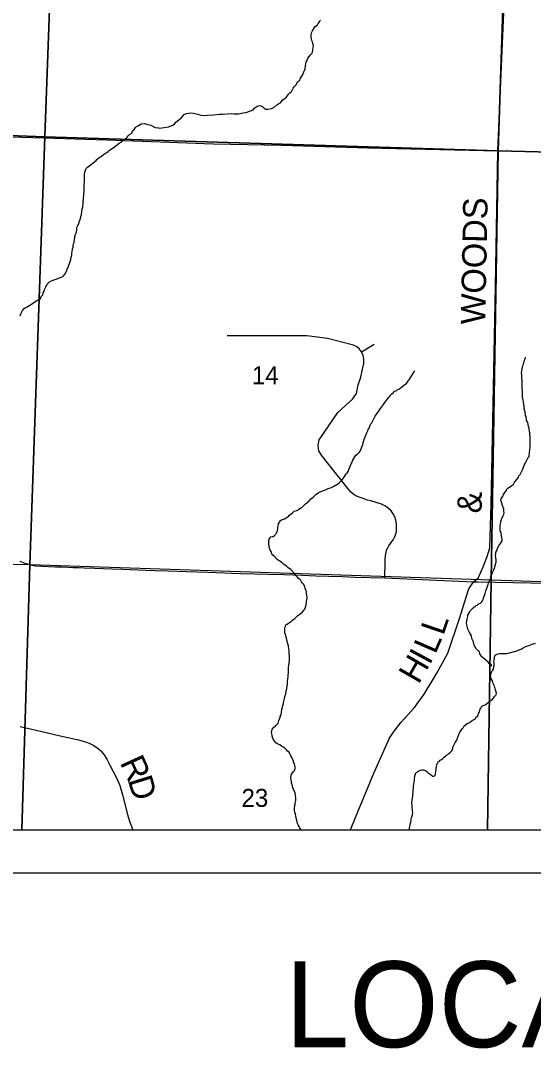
# Model space of a CAD drawing. Extents: x 0 to 34, y 0 to 22.
# Drawn here: x 3.811 to 5.004, y 13.591 to 15.984 of the extents above; entities that cross this region are included whole.
import ezdxf

# ---------------------------------------------------------------- set-up
doc = ezdxf.new("R2010")
doc.units = 0
for name, color, linetype in [('Default', 7, 'Continuous'), ('GM_X_County_Road', 7, 'Continuous'), ('GM_X_County_Road_Text', 7, 'Continuous'), ('GM_X_Minor_River', 7, 'Continuous'), ('GM_X_Section', 7, 'Continuous'), ('GM_X_Section_Text', 7, 'Continuous'), ('GM_X_Township_Road', 7, 'Continuous'), ('SH_Data', 7, 'Continuous'), ('SH_Text', 7, 'Continuous')]:
    doc.layers.add(name, color=color, linetype=linetype)

msp = doc.modelspace()

# ---------------------------------------------------------------- linework, layer by layer
at = {"layer": 'Default'}
msp.add_lwpolyline([(5.0396, 17.6997), (4.98, 17.7015), (4.9045, 17.7039), (4.763, 17.7084), (4.6735, 17.7102), (4.6237, 17.7121), (4.506, 17.7155), (4.4203, 17.718), (4.2769, 17.7222), (4.1969, 17.7246), (4.1354, 17.7264), (4.1238, 17.7269), (4.1165, 17.7286), (3.9904, 17.7296), (3.7662, 17.7368), (3.4544, 17.7458), (3.1037, 17.7609), (2.976, 17.7664), (2.8305, 17.7727), (2.1, 17.8044), (2.1, 14.1), (5.898, 14.1)], dxfattribs=at)
for points in [[(2.801, 14.1), (3.8138, 14.1), (3.832, 14.7167), (2.8159, 14.7367)], [(3.8138, 14.1), (4.8974, 14.1), (4.9059, 14.6808), (3.832, 14.7167)], [(4.8974, 14.1), (5.8991, 14.1), (5.9159, 14.648), (4.9059, 14.6808)]]:
    msp.add_lwpolyline(points, close=True, dxfattribs=at)
at = {"layer": 'GM_X_County_Road'}
for points in [[(4.5787, 14.1), (4.5919, 14.1324), (4.6325, 14.2319), (4.6697, 14.3133), (4.6805, 14.3297), (4.6967, 14.3508), (4.7273, 14.3845), (4.7499, 14.4158), (4.7797, 14.4649), (4.8049, 14.5109), (4.8331, 14.5941), (4.848, 14.6414), (4.8542, 14.6607), (4.865, 14.6774), (4.8766, 14.6871), (4.8871, 14.7118), (4.8966, 14.7365), (4.9028, 14.7566), (4.9058, 14.8573), (4.916, 15.3658), (4.9217, 15.6805), (4.9358, 16.0016), (4.9423, 16.1873)], [(3.809, 14.7251), (3.8203, 14.7206), (3.8369, 14.7159), (3.8457, 14.7142), (3.8759, 14.7126), (3.891, 14.7124), (3.9054, 14.7119), (3.9206, 14.7112), (3.9331, 14.7109), (3.9466, 14.7106), (3.9586, 14.71), (3.9826, 14.7091), (4.0229, 14.7076), (4.0487, 14.7069), (4.1027, 14.7047), (4.1237, 14.704), (4.1544, 14.7028), (4.1965, 14.7012), (4.2463, 14.6997), (4.3233, 14.697), (4.3858, 14.6949), (4.4243, 14.694), (4.4668, 14.6925), (4.4978, 14.6914), (4.5278, 14.6907), (4.5599, 14.6894), (4.5895, 14.6883), (4.6585, 14.6866), (4.865, 14.6774), (4.8751, 14.6772)], [(4.8751, 14.6772), (5.0801, 14.6733), (5.2252, 14.6674), (5.4111, 14.6617), (5.533, 14.6576), (5.764, 14.6502), (5.8816, 14.6485), (5.9165, 14.6499)], [(3.81, 14.3408), (3.8603, 14.3289), (3.9027, 14.319), (3.9456, 14.309), (3.964, 14.3037), (3.9721, 14.3006), (3.9794, 14.2972), (3.9859, 14.2932), (3.9917, 14.2887), (3.9973, 14.2839), (4.0049, 14.2747), (4.012, 14.2627), (4.0186, 14.2503), (4.0261, 14.2359), (4.0344, 14.2195), (4.0417, 14.2027), (4.0482, 14.1814), (4.0544, 14.1569), (4.0591, 14.138), (4.065, 14.1174), (4.0716, 14.1)]]:
    msp.add_lwpolyline(points, dxfattribs=at)
at = {"layer": 'GM_X_Minor_River'}
for points in [[(4.3184, 15.7669), (4.328, 15.769), (4.336, 15.7699), (4.3456, 15.7742), (4.3517, 15.7764), (4.3549, 15.7797), (4.3587, 15.783), (4.3611, 15.7845), (4.3653, 15.7855), (4.3675, 15.7859), (4.3698, 15.7854), (4.3721, 15.7846), (4.3747, 15.783), (4.3769, 15.7807), (4.3818, 15.7775), (4.386, 15.7774), (4.3948, 15.7795), (4.3998, 15.7812), (4.4068, 15.7875), (4.4098, 15.7897), (4.416, 15.7926), (4.4211, 15.7993), (4.4242, 15.8019), (4.4292, 15.8052), (4.4343, 15.8127), (4.4374, 15.8156), (4.4413, 15.819), (4.4453, 15.8265), (4.4477, 15.8298), (4.4516, 15.8339), (4.4559, 15.8422), (4.4606, 15.8455), (4.4614, 15.8481), (4.4673, 15.8582), (4.4701, 15.865), (4.4714, 15.868), (4.473, 15.8718), (4.4739, 15.8793), (4.4747, 15.8824), (4.4748, 15.8846), (4.476, 15.8892), (4.4784, 15.8925), (4.4796, 15.8963), (4.4855, 15.9045), (4.4886, 15.9075), (4.4898, 15.9105), (4.4907, 15.9143), (4.4911, 15.9169), (4.492, 15.9211), (4.4921, 15.926), (4.491, 15.9302), (4.49, 15.9348), (4.4886, 15.9379), (4.4879, 15.9405), (4.4872, 15.9463), (4.4873, 15.9508), (4.4882, 15.9569), (4.4898, 15.9602), (4.4954, 15.9696), (4.5019, 15.974), (4.5032, 15.977), (4.5067, 15.9807), (4.5075, 15.983), (4.5091, 15.9852)], [(3.9183, 15.4022), (3.9188, 15.4048), (3.9207, 15.4074), (3.922, 15.4123), (3.9232, 15.4146), (3.9252, 15.4206), (3.926, 15.4229), (3.9273, 15.4274), (3.9277, 15.4301), (3.929, 15.4354), (3.9298, 15.4376), (3.9303, 15.4425), (3.9307, 15.4452), (3.9317, 15.4524), (3.9329, 15.4565), (3.9334, 15.4607), (3.9338, 15.4645), (3.9351, 15.4675), (3.936, 15.4755), (3.9372, 15.4781), (3.9373, 15.4815), (3.9389, 15.4879), (3.9405, 15.4913), (3.9414, 15.4966), (3.9415, 15.5004), (3.9427, 15.5038), (3.9436, 15.5065), (3.9455, 15.5091), (3.948, 15.5174), (3.9492, 15.5204), (3.9509, 15.5276), (3.9521, 15.5313), (3.9535, 15.54), (3.9539, 15.545), (3.9552, 15.5499), (3.9562, 15.5593), (3.9566, 15.5631), (3.9571, 15.5681), (3.9578, 15.5802), (3.9583, 15.5859), (3.9592, 15.6246), (3.9601, 15.6307), (3.9609, 15.633), (3.9637, 15.6394), (3.9668, 15.6423), (3.9719, 15.6467), (3.9765, 15.6501), (3.9792, 15.6519), (3.9843, 15.6563), (3.9866, 15.6585), (3.9882, 15.6608), (3.9936, 15.6652), (3.9982, 15.6674), (4.0048, 15.6729), (4.0075, 15.6747), (4.0145, 15.6795), (4.0179, 15.6821), (4.0261, 15.688), (4.04, 15.6983), (4.0473, 15.7034), (4.0508, 15.7063), (4.0566, 15.7092), (4.0613, 15.7156), (4.0644, 15.7185), (4.0694, 15.7218), (4.0722, 15.7282), (4.075, 15.7301), (4.0781, 15.7353), (4.0804, 15.7371), (4.0851, 15.7393), (4.0912, 15.7437), (4.0989, 15.7447), (4.1068, 15.7422), (4.114, 15.7405), (4.1241, 15.7353), (4.1317, 15.734), (4.134, 15.7335), (4.1447, 15.7348), (4.1546, 15.7364), (4.165, 15.7407), (4.1696, 15.744), (4.1716, 15.7467), (4.1797, 15.7533), (4.1847, 15.7566), (4.1859, 15.7592), (4.1918, 15.7652), (4.1971, 15.7673), (4.2059, 15.769), (4.2127, 15.768), (4.223, 15.7659), (4.2282, 15.7642), (4.2313, 15.7638), (4.2396, 15.7632), (4.2461, 15.7634), (4.2602, 15.7642), (4.2735, 15.7662), (4.2804, 15.7664), (4.2914, 15.7668), (4.3017, 15.7674), (4.3074, 15.7668), (4.3184, 15.7669)], [(3.8094, 15.2962), (3.8111, 15.3015), (3.8151, 15.309), (3.8193, 15.3138), (3.8217, 15.3153), (3.8263, 15.3174), (3.8382, 15.3255), (3.8437, 15.3292), (3.8517, 15.3335), (3.854, 15.3346), (3.8568, 15.3368), (3.8595, 15.3421), (3.8623, 15.3454), (3.8635, 15.3499), (3.8647, 15.3526), (3.8667, 15.3578), (3.8692, 15.3639), (3.8719, 15.368), (3.8739, 15.3725), (3.8762, 15.374), (3.879, 15.3762), (3.8828, 15.378), (3.8878, 15.3801), (3.8909, 15.3812), (3.8974, 15.3837), (3.9035, 15.3854), (3.9089, 15.3883), (3.9116, 15.3906), (3.9136, 15.3932), (3.9159, 15.3969), (3.9183, 15.4022)], [(4.9292, 14.8703), (4.9319, 14.8744), (4.9335, 14.8777), (4.9343, 14.8804), (4.9379, 14.8852), (4.9398, 14.8886), (4.9414, 14.8909), (4.9438, 14.895), (4.9465, 14.8964), (4.9492, 14.8986), (4.9531, 14.9008), (4.9577, 14.9049), (4.9605, 14.909), (4.9656, 14.9157), (4.9695, 14.9206), (4.9703, 14.924), (4.9731, 14.9273), (4.9754, 14.9318), (4.9786, 14.9382), (4.9819, 14.9469), (4.9839, 14.9506), (4.9871, 14.9574), (4.989, 14.9604), (4.9918, 14.9664), (4.9942, 14.9694), (4.9946, 14.9716), (4.9951, 14.9758), (4.9952, 14.9796), (4.996, 14.983), (4.9961, 14.9857), (4.9965, 14.9898), (4.9966, 14.994), (4.9967, 14.9978), (4.997, 15.0088), (4.9967, 15.0123), (4.9968, 15.0157), (4.9961, 15.0195), (4.9958, 15.0241), (4.9951, 15.0264), (4.9942, 15.0351), (4.9927, 15.0386), (4.9917, 15.0436), (4.991, 15.0481), (4.9899, 15.0505), (4.9885, 15.0532), (4.9882, 15.0554), (4.9872, 15.0619), (4.9861, 15.0646), (4.9861, 15.0669), (4.9854, 15.0696), (4.9848, 15.073), (4.983, 15.0795), (4.9824, 15.086), (4.9817, 15.0887), (4.9811, 15.0967), (4.9801, 15.1001), (4.9794, 15.1043), (4.9791, 15.1066), (4.9791, 15.1089), (4.9788, 15.1123), (4.9786, 15.1207), (4.9787, 15.1241), (4.9784, 15.1272), (4.9781, 15.1298), (4.9781, 15.1321), (4.9779, 15.1401), (4.978, 15.1431), (4.9777, 15.1469), (4.9774, 15.1504), (4.9776, 15.1568), (4.9772, 15.1591), (4.9769, 15.1629), (4.9774, 15.1675), (4.9783, 15.1739), (4.9788, 15.1762), (4.9792, 15.1788), (4.9804, 15.1815), (4.9812, 15.1845), (4.9817, 15.1871), (4.9837, 15.1935), (4.9849, 15.1962), (4.9858, 15.2003)], [(4.5677, 14.9287), (4.5716, 14.932), (4.5739, 14.9354), (4.5748, 14.9384), (4.5768, 14.944), (4.5796, 14.9504), (4.5808, 14.9527), (4.5824, 14.9564), (4.584, 14.9606), (4.586, 14.9643), (4.5884, 14.9681), (4.5911, 14.9718), (4.5946, 14.9748), (4.5989, 14.9785), (4.6012, 14.9814), (4.6036, 14.9871), (4.6044, 14.9893), (4.6069, 14.9969), (4.6078, 15.001), (4.6098, 15.0059), (4.6106, 15.0086), (4.611, 15.0108), (4.613, 15.0146), (4.6138, 15.0172), (4.615, 15.0203), (4.6167, 15.024), (4.6187, 15.0285), (4.6195, 15.0319), (4.6222, 15.0353), (4.6243, 15.0417), (4.6259, 15.0447), (4.6282, 15.0473), (4.6298, 15.0503), (4.6314, 15.0537), (4.6338, 15.0582), (4.6362, 15.0631), (4.639, 15.0679), (4.6421, 15.0717), (4.6452, 15.0761), (4.6484, 15.081), (4.6554, 15.09), (4.6582, 15.0945), (4.6621, 15.1004), (4.6699, 15.1094), (4.6727, 15.1123), (4.6746, 15.1153), (4.6785, 15.1179), (4.6809, 15.1209), (4.6851, 15.1223), (4.687, 15.1245), (4.6912, 15.1259), (4.6943, 15.1278), (4.6963, 15.13), (4.7025, 15.1348), (4.7052, 15.1366), (4.709, 15.1392), (4.7126, 15.1452), (4.7153, 15.1478), (4.7193, 15.1541), (4.7212, 15.1575), (4.7248, 15.1635), (4.728, 15.1695)], [(4.4773, 14.6355), (4.4774, 14.6393), (4.4772, 14.6458), (4.4765, 14.6496), (4.4762, 14.6519), (4.4759, 14.6546), (4.4748, 14.6576), (4.473, 14.6622), (4.4719, 14.6657), (4.4698, 14.6707), (4.4668, 14.6745), (4.4646, 14.6769), (4.4628, 14.6804), (4.4609, 14.6827), (4.4575, 14.685), (4.4553, 14.6878), (4.4523, 14.6909), (4.4501, 14.6944), (4.4457, 14.699), (4.4398, 14.706), (4.4338, 14.7096), (4.43, 14.7127), (4.427, 14.7151), (4.4237, 14.7178), (4.4199, 14.7206), (4.4177, 14.7225), (4.4132, 14.7261), (4.4102, 14.7277), (4.4076, 14.7296), (4.4013, 14.7362), (4.3979, 14.7394), (4.3957, 14.7425), (4.3943, 14.7455), (4.3936, 14.7482), (4.3917, 14.7506), (4.3892, 14.7586), (4.3889, 14.7616), (4.3886, 14.7643), (4.3888, 14.7742), (4.3893, 14.7765), (4.3905, 14.7791), (4.3932, 14.7817), (4.3959, 14.7824), (4.3982, 14.7831), (4.402, 14.7853), (4.4044, 14.7879), (4.406, 14.7913), (4.4079, 14.7939), (4.4084, 14.7965), (4.4092, 14.8003), (4.4093, 14.8041), (4.4101, 14.8067), (4.411, 14.812), (4.4122, 14.8147), (4.4138, 14.8177), (4.4154, 14.8199), (4.4192, 14.8225), (4.4231, 14.8235), (4.4265, 14.825), (4.4288, 14.826), (4.4315, 14.8279), (4.4338, 14.8286), (4.4366, 14.8323), (4.4408, 14.8356), (4.4439, 14.8382), (4.4478, 14.8415), (4.4539, 14.8433), (4.4562, 14.8444), (4.4586, 14.8462), (4.4624, 14.8488), (4.4651, 14.8502), (4.4713, 14.8562), (4.4737, 14.8592), (4.4776, 14.8617), (4.4822, 14.8658), (4.4861, 14.8706), (4.4884, 14.8721), (4.4923, 14.8754), (4.4946, 14.8773), (4.4981, 14.8806), (4.5035, 14.8843), (4.5093, 14.8879), (4.5143, 14.8893), (4.5174, 14.8904), (4.5205, 14.8918), (4.5231, 14.8929), (4.5262, 14.8943), (4.5289, 14.8954), (4.5343, 14.8972), (4.537, 14.8983), (4.54, 14.8997), (4.5439, 14.9023), (4.5462, 14.903), (4.5493, 14.9056), (4.5532, 14.9085), (4.5563, 14.9118), (4.5594, 14.9148), (4.5617, 14.9182), (4.5633, 14.9204), (4.5661, 14.9245), (4.5677, 14.9287)], [(4.9077, 14.4811), (4.907, 14.4838), (4.9048, 14.4858), (4.9014, 14.4874), (4.8988, 14.4901), (4.8924, 14.4959), (4.8883, 14.4995), (4.8846, 14.5026), (4.8798, 14.5096), (4.8788, 14.5145), (4.8713, 14.5212), (4.8677, 14.527), (4.867, 14.5293), (4.8659, 14.532), (4.8645, 14.5377), (4.8609, 14.545), (4.8599, 14.5515), (4.8555, 14.5596), (4.8519, 14.5673), (4.8508, 14.5707), (4.8494, 14.5772), (4.8488, 14.5814), (4.8492, 14.5856), (4.8493, 14.5883), (4.8501, 14.5905), (4.8518, 14.5962), (4.8518, 14.5996), (4.8542, 14.6033), (4.8562, 14.6071), (4.857, 14.6097), (4.8605, 14.6127), (4.864, 14.6168), (4.8698, 14.6216), (4.8733, 14.623), (4.8756, 14.6252), (4.8787, 14.6267), (4.8814, 14.6274), (4.8837, 14.6296), (4.8861, 14.633), (4.8877, 14.6363), (4.8881, 14.639), (4.8897, 14.6435), (4.8914, 14.6477), (4.8918, 14.6499), (4.8934, 14.656), (4.8951, 14.6609), (4.8963, 14.6635), (4.8975, 14.6669), (4.8991, 14.671), (4.8999, 14.6741), (4.9008, 14.6763), (4.904, 14.6846), (4.9052, 14.6887), (4.906, 14.6914), (4.9073, 14.6948), (4.9081, 14.6974), (4.9108, 14.7019), (4.9121, 14.7053), (4.9137, 14.7094), (4.9141, 14.7121), (4.9158, 14.7178), (4.9166, 14.7208), (4.9178, 14.723), (4.9179, 14.7268), (4.9176, 14.7295), (4.9169, 14.7318), (4.9165, 14.7345), (4.9162, 14.7375), (4.9167, 14.7432), (4.9168, 14.7462), (4.9188, 14.7496), (4.9196, 14.7519), (4.9208, 14.7556), (4.9236, 14.7613), (4.9279, 14.7665), (4.9303, 14.7702), (4.9315, 14.7725), (4.9312, 14.7759), (4.9305, 14.7816), (4.9295, 14.7855), (4.9296, 14.7881), (4.9271, 14.7962), (4.9268, 14.8004), (4.9265, 14.8049), (4.927, 14.8091), (4.9275, 14.8125), (4.9283, 14.8155), (4.9287, 14.8178), (4.9303, 14.8223), (4.9316, 14.8272), (4.9336, 14.8298), (4.9348, 14.8329), (4.9352, 14.8351), (4.936, 14.8381), (4.9357, 14.8423), (4.9354, 14.8461), (4.9333, 14.8527), (4.9301, 14.8626), (4.929, 14.8653), (4.9283, 14.8676), (4.9292, 14.8703)], [(4.4397, 14.2723), (4.4382, 14.275), (4.4357, 14.2803), (4.432, 14.2831), (4.4294, 14.2862), (4.4249, 14.2905), (4.4227, 14.2921), (4.42, 14.2933), (4.4178, 14.2949), (4.414, 14.2976), (4.4099, 14.2996), (4.4073, 14.3008), (4.405, 14.3024), (4.4028, 14.3055), (4.401, 14.3078), (4.3988, 14.3113), (4.3966, 14.3178), (4.3959, 14.3205), (4.3949, 14.3266), (4.3954, 14.33), (4.3966, 14.3334), (4.3978, 14.3356), (4.4002, 14.3386), (4.4032, 14.3408), (4.4056, 14.3434), (4.4076, 14.346), (4.4099, 14.3483), (4.4119, 14.3543), (4.4135, 14.3581), (4.4148, 14.3614), (4.4152, 14.3637), (4.4168, 14.3679), (4.4181, 14.3735), (4.419, 14.38), (4.4194, 14.3822), (4.4211, 14.3894), (4.4223, 14.394), (4.4228, 14.3962), (4.4236, 14.3992), (4.4249, 14.4053), (4.4258, 14.4106), (4.4278, 14.4166), (4.4291, 14.4231), (4.4304, 14.428), (4.4304, 14.4306), (4.4313, 14.4344), (4.4318, 14.4401), (4.4322, 14.4435), (4.4328, 14.4519), (4.4333, 14.4556), (4.4334, 14.4598), (4.4339, 14.4659), (4.434, 14.4693), (4.4344, 14.4716), (4.4345, 14.4761), (4.4346, 14.4788), (4.4354, 14.4833), (4.4359, 14.4871), (4.436, 14.4898), (4.4364, 14.4936), (4.4365, 14.4962), (4.4362, 14.4997), (4.4366, 14.5027), (4.4363, 14.5054), (4.436, 14.5096), (4.4361, 14.5118), (4.4358, 14.5153), (4.4352, 14.5229), (4.4341, 14.526), (4.4342, 14.5282), (4.4328, 14.5328), (4.4321, 14.5355), (4.431, 14.5393), (4.4303, 14.5416), (4.4293, 14.547), (4.4279, 14.5516), (4.4272, 14.5546), (4.4261, 14.5585), (4.4258, 14.563), (4.4255, 14.5665), (4.4256, 14.5695), (4.4268, 14.5721), (4.4276, 14.5744), (4.4284, 14.577), (4.4308, 14.5789), (4.4339, 14.5811), (4.4366, 14.5825), (4.4416, 14.5858), (4.4443, 14.5888), (4.4489, 14.5921), (4.4556, 14.5988), (4.461, 14.6017), (4.4672, 14.6076), (4.4703, 14.611), (4.4723, 14.6136), (4.4735, 14.6181), (4.4747, 14.6204), (4.4755, 14.6241), (4.4764, 14.6294), (4.4765, 14.6317), (4.4773, 14.6355)], [(4.8142, 14.2835), (4.8157, 14.2861), (4.8178, 14.294), (4.8194, 14.297), (4.8222, 14.3034), (4.8246, 14.306), (4.8258, 14.3083), (4.8266, 14.3113), (4.8282, 14.3158), (4.831, 14.3218), (4.8326, 14.3252), (4.833, 14.3275), (4.8354, 14.3305), (4.8366, 14.3327), (4.8386, 14.3353), (4.8405, 14.3376), (4.8433, 14.3421), (4.8499, 14.3472), (4.8522, 14.3483), (4.8556, 14.3501), (4.8587, 14.352), (4.8626, 14.3549), (4.866, 14.3571), (4.8684, 14.3582), (4.8703, 14.3612), (4.8746, 14.3649), (4.8758, 14.3679), (4.8766, 14.3709), (4.8786, 14.3746), (4.8803, 14.3807), (4.8815, 14.3833), (4.8827, 14.3856), (4.8854, 14.3882), (4.8877, 14.3892), (4.8904, 14.3903), (4.8935, 14.3918), (4.9001, 14.3973), (4.9024, 14.3991), (4.9062, 14.4017), (4.9086, 14.4028), (4.9125, 14.408), (4.914, 14.4103), (4.9172, 14.4144), (4.9184, 14.417), (4.9173, 14.4208), (4.9156, 14.4285), (4.9138, 14.4342), (4.9109, 14.4404), (4.9088, 14.4465), (4.9062, 14.4515), (4.9048, 14.4553), (4.9045, 14.4584), (4.9049, 14.4607), (4.9054, 14.4633), (4.907, 14.4667), (4.9082, 14.4697), (4.9098, 14.4719), (4.911, 14.4742), (4.9122, 14.4791), (4.9131, 14.4833), (4.9131, 14.4855), (4.9128, 14.489), (4.9121, 14.492), (4.9126, 14.4947), (4.9138, 14.4977), (4.9134, 14.5), (4.9135, 14.5023), (4.9147, 14.5045), (4.9167, 14.5071), (4.9197, 14.509), (4.922, 14.5097), (4.9255, 14.5103), (4.9289, 14.5106), (4.9335, 14.5101), (4.9384, 14.5104), (4.9426, 14.5107), (4.9636, 14.5158), (4.9694, 14.518), (4.9728, 14.5194), (4.9774, 14.5216), (4.9813, 14.5245), (4.9867, 14.5263), (4.9913, 14.5281), (4.9944, 14.5292), (5.0016, 14.532), (5.0089, 14.5345)], [(4.4636, 14.1), (4.462, 14.1018), (4.4602, 14.1049), (4.4587, 14.1076), (4.4569, 14.1111), (4.4555, 14.1145), (4.4544, 14.1183), (4.4533, 14.1206), (4.4524, 14.1283), (4.4517, 14.131), (4.4503, 14.1367), (4.4489, 14.1413), (4.4485, 14.1443), (4.4482, 14.147), (4.4483, 14.1512), (4.4488, 14.1538), (4.4492, 14.1569), (4.4497, 14.1595), (4.4501, 14.1618), (4.4509, 14.1652), (4.4514, 14.1678), (4.4515, 14.1754), (4.4509, 14.18), (4.4495, 14.185), (4.4485, 14.1899), (4.447, 14.1923), (4.4459, 14.1953), (4.4445, 14.198), (4.4427, 14.2057), (4.4413, 14.2095), (4.441, 14.2129), (4.4407, 14.2156), (4.44, 14.2198), (4.4402, 14.227), (4.4414, 14.2296), (4.4445, 14.2334), (4.4461, 14.236), (4.4492, 14.239), (4.4497, 14.2431), (4.4494, 14.2466), (4.4487, 14.2496), (4.4484, 14.2527), (4.4473, 14.255), (4.4462, 14.2577), (4.4459, 14.2599), (4.4437, 14.2649), (4.4419, 14.2684), (4.4397, 14.2723)], [(4.7148, 14.1), (4.7161, 14.1039), (4.717, 14.108), (4.7174, 14.1103), (4.7178, 14.1137), (4.7187, 14.1171), (4.72, 14.1243), (4.7208, 14.1281), (4.7225, 14.1337), (4.7229, 14.136), (4.7234, 14.1394), (4.7231, 14.1444), (4.7228, 14.147), (4.7221, 14.1501), (4.7218, 14.1547), (4.7219, 14.1569), (4.7216, 14.1623), (4.7222, 14.1698), (4.723, 14.1744), (4.7235, 14.1782), (4.7236, 14.1812), (4.7245, 14.188), (4.7248, 14.2006), (4.7257, 14.207), (4.7266, 14.2112), (4.7274, 14.2157), (4.7275, 14.218), (4.7284, 14.2256), (4.7288, 14.2278), (4.7308, 14.2323), (4.7351, 14.2357), (4.7409, 14.2386), (4.7443, 14.2396), (4.7481, 14.2399), (4.7515, 14.2391), (4.7564, 14.2355), (4.7594, 14.2328), (4.762, 14.2312), (4.7642, 14.2292), (4.7676, 14.2261), (4.7702, 14.2245), (4.7725, 14.2245), (4.7756, 14.2267), (4.7764, 14.2305), (4.7769, 14.2346), (4.7782, 14.2411), (4.7784, 14.2479), (4.7792, 14.2513), (4.78, 14.2536), (4.7828, 14.258), (4.7855, 14.2595), (4.7874, 14.2617), (4.7901, 14.2632), (4.7936, 14.2658), (4.7967, 14.2687), (4.7994, 14.2717), (4.8029, 14.2743), (4.8052, 14.2754), (4.8072, 14.2776), (4.811, 14.2805), (4.8142, 14.2835)]]:
    msp.add_lwpolyline(points, dxfattribs=at)
at = {"layer": 'GM_X_Section'}
for points in [[(2.9224, 16.7901), (3.47, 16.7707), (3.4696, 16.7535), (3.904, 16.7335), (3.8671, 15.713), (2.854, 15.751)], [(3.904, 16.7335), (4.9556, 16.6985), (4.9226, 15.6806), (3.8671, 15.713)], [(4.9556, 16.6985), (5.9708, 16.6629), (5.9463, 15.655), (4.9226, 15.6806)], [(2.854, 15.751), (3.8671, 15.713), (3.832, 14.7167), (2.8159, 14.7367)], [(4.9226, 15.6806), (4.9059, 14.6808), (3.832, 14.7167), (3.8671, 15.713)], [(5.9463, 15.655), (5.9159, 14.648), (4.9059, 14.6808), (4.9226, 15.6806)]]:
    msp.add_lwpolyline(points, close=True, dxfattribs=at)
at = {"layer": 'GM_X_Township_Road'}
msp.add_line((4.6043, 15.213), (4.6337, 15.2304), dxfattribs=at)
for points in [[(2.8483, 15.7449), (3.2111, 15.7342), (3.4418, 15.7236), (3.5498, 15.7201), (3.839, 15.7116), (4.0111, 15.7063), (4.2594, 15.6971), (4.4176, 15.6936), (4.6181, 15.6876), (4.9217, 15.6805)], [(4.6585, 14.6866), (4.6591, 14.7242), (4.6591, 14.7271), (4.6593, 14.7314), (4.6598, 14.7352), (4.6603, 14.7383), (4.6612, 14.7457), (4.6626, 14.7508), (4.6652, 14.7565), (4.6677, 14.7609), (4.6713, 14.7663), (4.6777, 14.7753), (4.6809, 14.7815), (4.6833, 14.7866), (4.6852, 14.7911), (4.6857, 14.7954), (4.6858, 14.7998), (4.6855, 14.8052), (4.6856, 14.8126), (4.6842, 14.8208), (4.6814, 14.8286), (4.6777, 14.8358), (4.6731, 14.8423), (4.6669, 14.8482), (4.6602, 14.8532), (4.6508, 14.8579), (4.6379, 14.8616), (4.6255, 14.866), (4.6173, 14.8677), (4.6102, 14.8703), (4.6035, 14.8725), (4.5967, 14.8755), (4.5912, 14.8778), (4.5861, 14.8807), (4.5793, 14.8857), (4.5216, 14.9582), (4.5108, 14.9718), (4.5051, 14.9826), (4.5031, 14.9948), (4.506, 15.0079), (4.5494, 15.0718), (4.5673, 15.0888), (4.5835, 15.1027), (4.5928, 15.1157), (4.5966, 15.1356), (4.6024, 15.1541), (4.6065, 15.1722), (4.6093, 15.1859), (4.6098, 15.1966), (4.6081, 15.2042), (4.6043, 15.213), (4.5993, 15.2189), (4.5931, 15.2246), (4.5853, 15.2281), (4.5253, 15.2438), (4.4766, 15.2497), (4.2913, 15.2497)]]:
    msp.add_lwpolyline(points, dxfattribs=at)
at = {"layer": 'SH_Data'}
for p, q in [((2.1, 14.1), (8.9, 14.1)), ((2, 14), (9, 14))]:
    msp.add_line(p, q, dxfattribs=at)

# ---------------------------------------------------------------- texts
at = {"layer": 'GM_X_County_Road_Text'}
for s, height, rotation, p in [('WOODS', 0.05682, 88.8803, (4.8921, 15.2761)), ('&', 0.0568, 89.1475, (4.8837, 14.8364)), ('L', 0.0568, 71.1335, (4.7946, 14.5505)), ('L', 0.0568, 66.4722, (4.7759, 14.5069)), ('H', 0.0568, 60.0454, (4.7368, 14.437)), ('I', 0.0568, 61.7051, (4.7626, 14.4818)), ('R', 0.0568, 294.4391, (4.0411, 14.2567)), ('D', 0.0568, 287.1804, (4.0597, 14.216))]:
    msp.add_text(s, height=height, rotation=rotation, dxfattribs=at).set_placement(p)
at = {"layer": 'GM_X_Section_Text'}
for s, p in [('14', (4.349, 15.1374)), ('23', (4.3249, 14.1533))]:
    msp.add_text(s, height=0.04186, rotation=0, dxfattribs=at).set_placement(p)
at = {"layer": 'SH_Text'}
msp.add_text('LOCATION MAP', height=0.2, dxfattribs=at).set_placement((4.4269, 13.5937))

doc.saveas('drawing.dxf')
